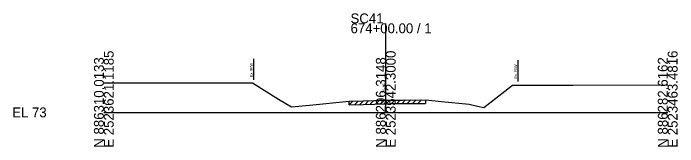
# Model space of a CAD drawing. Extents: x -26 to 183, y -10 to 24021.
# Drawn here: x -25.7 to 162.8, y 6490.3 to 6528 of the extents above; entities that cross this region are included whole.
import ezdxf

# ---------------------------------------------------------------- set-up
doc = ezdxf.new("R2010")
doc.units = 0
for name, color, linetype in [('RD_GPK_XS_Cell', 7, 'Continuous'), ('RD_XS_ExGround', 7, 'Continuous'), ('RD_XS_ExPaveRet', 7, 'Continuous'), ('RD_XS_ExRW', 7, 'Continuous'), ('RD_XS_TX_Elev_EX', 7, 'Continuous')]:
    doc.layers.add(name, color=color, linetype=linetype)

msp = doc.modelspace()

# ---------------------------------------------------------------- linework, layer by layer
at = {"layer": 'RD_GPK_XS_Cell'}
for p, q in [((80, 6500), (80, 6525.19)), ((0, 6500), (80, 6500)), ((80, 6500), (160, 6500))]:
    msp.add_line(p, q, dxfattribs=at)
at = {"layer": 'RD_XS_ExGround'}
for p, q in [((0, 6508.4), (19.38, 6508.39)), ((19.38, 6508.39), (35.29, 6508.34)), ((35.29, 6508.34), (42.17, 6508.37)), ((42.17, 6508.37), (49.6, 6503.71)), ((112.93, 6505.33), (115.99, 6507.75)), ((115.99, 6507.75), (133.08, 6507.73)), ((133.08, 6507.73), (160, 6507.76)), ((107.79, 6501.39), (112.93, 6505.33)), ((49.6, 6503.71), (53.28, 6501.54)), ((58.34, 6502.01), (69.61, 6503.14)), ((69.61, 6503.14), (73.62, 6503.26)), ((73.62, 6503.26), (80, 6503.45)), ((80, 6503.45), (81.16, 6503.48)), ((81.16, 6503.48), (84.77, 6503.5)), ((84.77, 6503.5), (91.28, 6503.54)), ((91.28, 6503.54), (95.86, 6503.1)), ((95.86, 6503.1), (103.67, 6502.34)), ((53.28, 6501.54), (58.34, 6502.01)), ((103.67, 6502.34), (106.07, 6501.79)), ((106.07, 6501.79), (107.79, 6501.39))]:
    msp.add_line(p, q, dxfattribs=at)
at = {"layer": 'RD_XS_ExPaveRet'}
for p, q in [((69.61, 6502.14), (70.64, 6503.17)), ((69.61, 6502.14), (69.61, 6503.14)), ((71.11, 6502.18), (72.14, 6503.21)), ((72.61, 6502.23), (73.64, 6503.26)), ((74.11, 6502.27), (75.14, 6503.3)), ((75.61, 6502.32), (76.64, 6503.35)), ((77.11, 6502.36), (78.14, 6503.39)), ((78.61, 6502.41), (79.64, 6503.44)), ((80.11, 6502.45), (81.14, 6503.48)), ((81.16, 6502.48), (84.77, 6502.5)), ((81.61, 6502.48), (82.61, 6503.49)), ((83.11, 6502.49), (84.11, 6503.5)), ((84.61, 6502.5), (85.61, 6503.51)), ((84.77, 6502.5), (91.28, 6502.54)), ((86.11, 6502.51), (87.11, 6503.52)), ((87.61, 6502.52), (88.61, 6503.53)), ((89.11, 6502.53), (90.11, 6503.54)), ((91.28, 6503.54), (91.28, 6502.54)), ((69.61, 6502.14), (73.62, 6502.26)), ((73.62, 6502.26), (80, 6502.45)), ((80, 6502.45), (81.16, 6502.48))]:
    msp.add_line(p, q, dxfattribs=at)
at = {"layer": 'RD_XS_ExRW'}
for p, q in [((42.5, 6515.17), (42.5, 6509.17)), ((117.5, 6514.75), (117.5, 6508.75))]:
    msp.add_line(p, q, dxfattribs=at)

# ---------------------------------------------------------------- texts
at = {"layer": 'RD_GPK_XS_Cell'}
for s, p in [('SC41', (70, 6525.19)), ('674+00.00 / 1', (70, 6522.39)), ('EL 73', (-26, 6498.6))]:
    msp.add_text(s, height=2.8, dxfattribs=at).set_placement(p)
for s, p in [('E 2523621.1185', (2.8, 6490)), ('E 2523542.3000', (82.8, 6490)), ('E 2523463.4816', (162.8, 6490)), ('N 886310.0133', (0, 6490)), ('N 886296.3148', (80, 6490)), ('N 886282.6162', (160, 6490))]:
    msp.add_text(s, height=2.8, rotation=90, dxfattribs=at).set_placement(p)
at = {"layer": 'RD_XS_ExRW'}
for p in [(42.25, 6509.95), (117.25, 6509.53)]:
    msp.add_text('Ex. R/W ', height=0.8, rotation=90, dxfattribs=at).set_placement(p)
at = {"layer": 'RD_XS_TX_Elev_EX'}
msp.add_text('76.45', height=0.8, rotation=90, dxfattribs=at).set_placement((79.9, 6505.45))

doc.saveas('drawing.dxf')
